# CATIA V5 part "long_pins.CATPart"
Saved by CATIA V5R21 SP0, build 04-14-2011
Part number: long_pins
Bounding box of the stored display mesh (mm): x -10 to 10, y -10 to 10, z -100 to 0
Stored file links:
  C:\Users\swlee\Desktop\long_pins.CATPart
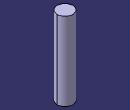
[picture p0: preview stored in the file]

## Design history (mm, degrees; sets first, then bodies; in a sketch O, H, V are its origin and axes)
AxisSystem1: origin (0, 0, 0), X (1, 0, 0), Y (0, 1, 0), Z (0, 0, 1)
Body1 (main body)
  Sketch1 on XY plane of AxisSystem1, origin (0, 0, 0), H (1, 0, 0), V (0, 1, 0)
    circle A1 centre (0, 0) radius 10
    radius A1 = 10
  Pad1: profile Sketch1, direction (0, 0, -1), length 100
